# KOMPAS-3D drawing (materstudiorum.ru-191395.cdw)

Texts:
  Умножитель Схема электрическая принципиальная
  Noncommercial version
  Текст на чертеже
  Размерные надписи
  Шероховатость
  Линия-выноска #1
  Линия-выноска #2
  Линия-выноска #3
  Отклонения формы и база
  Заголовок таблицы
  Ячейка таблицы
  Стрелка вида
  Обозначение изменения
  Фигурная скобка
  Номер узла
  Марка координационной оси
  VRCB
  Выносная надпись
  Обозначение узла
  Марка/позиционное обозначение с линией-выноской
  Марка/позиционное обозначение на линии
  Марка/позиционное обозначение без линии-выноски
  A3-1.cdt
  Умножитель
  Схема электрическая
  принципиальная
  Петров Д.Г.
Dimensions and other numbers on the sheet: 5093.077 000.000 Э3; 7; 1:2; 5093.077 000.000 Э3-; 0; 1; 2; 3; 4; 5; 6; 8; 9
